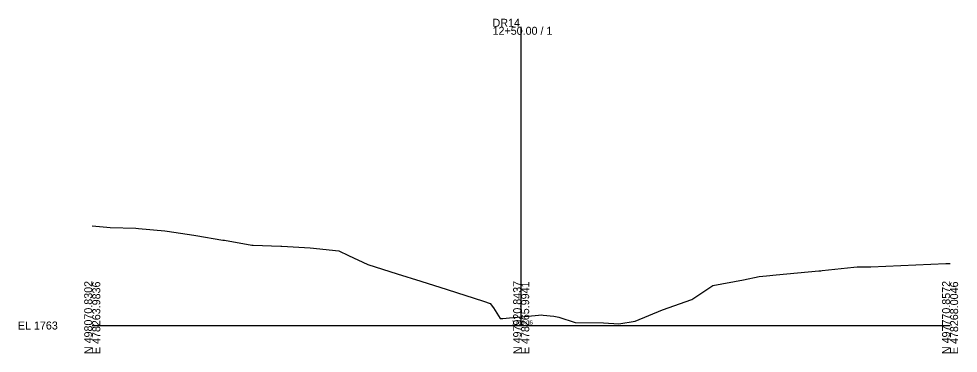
# Model space of a CAD drawing. Extents: x -26 to 303, y -59 to 3067.
# Drawn here: x -25.7 to 302.8, y 2490.3 to 2607.4 of the extents above; entities that cross this region are included whole.
import ezdxf

# ---------------------------------------------------------------- set-up
doc = ezdxf.new("R2010")
doc.units = 0
for name, color, linetype in [('Exist Cross Section Cell', 7, 'Continuous'), ('Exist XS Center Line Elevation Label', 7, 'Continuous'), ('Exist XS Ground Line', 7, 'Continuous')]:
    doc.layers.add(name, color=color, linetype=linetype)

msp = doc.modelspace()

# ---------------------------------------------------------------- linework, layer by layer
at = {"layer": 'Exist Cross Section Cell'}
for p, q in [((150, 2500), (150, 2604.56)), ((0, 2500), (150, 2500)), ((150, 2500), (300, 2500))]:
    msp.add_line(p, q, dxfattribs=at)
at = {"layer": 'Exist XS Ground Line'}
msp.add_lwpolyline([(0, 2534.85), (5.1, 2534.43), (6.23, 2534.34), (15.24, 2534.07), (16.23, 2533.98), (25.38, 2533.18), (26.24, 2533.08), (35.51, 2531.61), (36.24, 2531.52), (45.65, 2529.93), (46.24, 2529.83), (55.79, 2528.13), (56.25, 2528.12), (65.93, 2527.8), (66.25, 2527.78), (76.25, 2527.21), (86.25, 2526.16), (89.66, 2524.55), (96.33, 2521.4), (106.59, 2518.1), (114.9, 2515.53), (124.11, 2512.58), (136.86, 2508.55), (139.11, 2507.76), (140.37, 2506.17), (142.66, 2502.51), (143.62, 2502.44), (145.86, 2502.66), (150, 2503.06), (156.03, 2503.64), (156.97, 2503.71), (157.65, 2503.67), (161.38, 2503.32), (163.19, 2502.95), (168.94, 2501.03), (178.81, 2500.97), (184.21, 2500.6), (189.89, 2501.53), (199.47, 2505.49), (209.69, 2509.08), (217.04, 2514.06), (227.71, 2516.03), (233.2, 2517.11), (235.79, 2517.35), (239.22, 2517.8), (254.07, 2519.12), (254.75, 2519.18), (255.32, 2519.23), (266.31, 2520.48), (267.48, 2520.51), (272.3, 2520.59), (298.52, 2521.67), (300, 2521.66)], dxfattribs=at)

# ---------------------------------------------------------------- texts
at = {"layer": 'Exist Cross Section Cell'}
for s, p in [('DR14', (140, 2604.56)), ('12+50.00 / 1', (140, 2601.76)), ('EL 1763', (-26, 2498.6))]:
    msp.add_text(s, height=2.8, dxfattribs=at).set_placement(p)
for s, p in [('N 498070.8302', (0, 2490)), ('E 478263.9836', (2.8, 2490)), ('N 497920.8437', (150, 2490)), ('E 478265.9941', (152.8, 2490)), ('N 497770.8572', (300, 2490)), ('E 478268.0046', (302.8, 2490))]:
    msp.add_text(s, height=2.8, rotation=90, dxfattribs=at).set_placement(p)
at = {"layer": 'Exist XS Center Line Elevation Label'}
msp.add_text('1766.06', height=1.5, dxfattribs=at).set_placement((146.6, 2500.31))

doc.saveas('drawing.dxf')
